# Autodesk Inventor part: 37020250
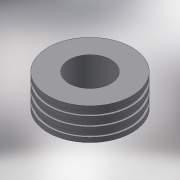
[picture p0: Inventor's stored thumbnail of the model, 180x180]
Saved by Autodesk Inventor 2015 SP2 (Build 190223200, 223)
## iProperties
Created: 2017-08
Part Number: 37020250
Material: Generic
Description: PLASSON MAN HOLE ADAPTOR 250
Document SubType Name: Modeling
Designer: Кирилл
Density: 1 g/cm^3
Appearance: Default
Author: Кирилл
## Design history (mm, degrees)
derived "37020-477207.ipt"
feature "Solid1::37020-477207.ipt"
tag "TaggingFeature1"
body "Solid1"
other parameters: "d0" = 135, "d6" = 54, "L_" = 135, "H_" = 54
